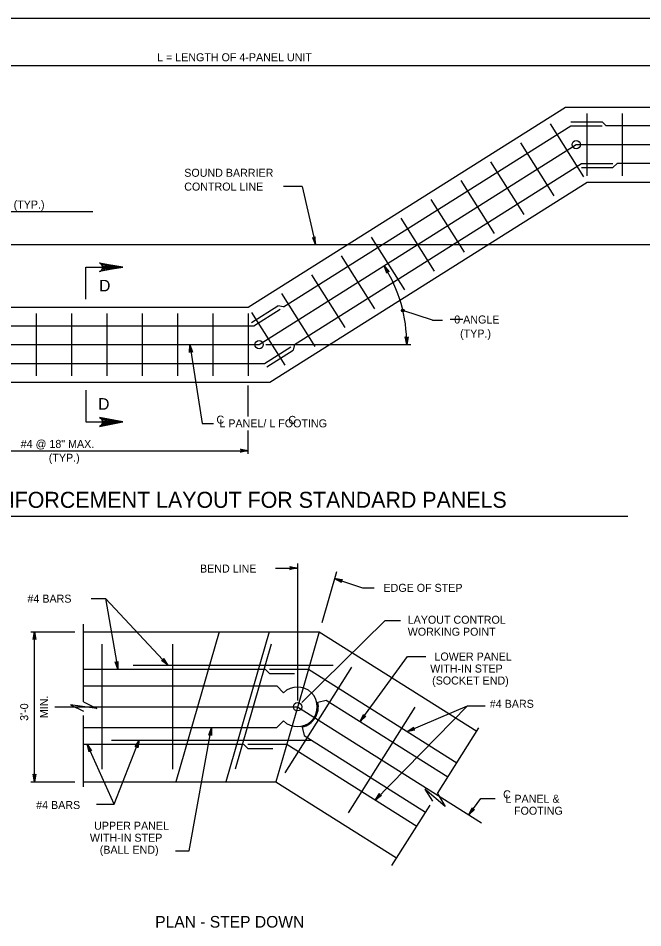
# Model space of a CAD drawing. Extents: x 3385 to 6532, y -616 to 1166.
# Drawn here: x 4903.8 to 5143.7, y -386.6 to -37.3 of the extents above; entities that cross this region are included whole.
import ezdxf

# ---------------------------------------------------------------- set-up
doc = ezdxf.new("R2010")
doc.units = 0
doc.layers.add('1', color=7, linetype='Continuous')
doc.layers.add('2', color=7, linetype='Continuous')

msp = doc.modelspace()

# ---------------------------------------------------------------- linework, layer by layer
at = {"layer": '1'}
for p, q in [((4730.55, -55.48), (5262.17, -55.48)), ((4992.2, -148.26), (5114.01, -71.46)), ((5114.01, -71.46), (5266.33, -71.46)), ((5122.33, -97.86), (5122.33, -73.86)), ((5135.9, -97.86), (5135.9, -73.86)), ((5005.79, -148.2), (5116.09, -78.66)), ((5121.05, -98.23), (5108.25, -77.93)), ((5116.09, -77.06), (5128.1, -77.06)), ((5116.09, -78.66), (5128.1, -78.66)), ((5129.7, -78.66), (5128.1, -77.06)), ((5264.25, -78.66), (5129.7, -78.66)), ((4996.36, -162.66), (5118.17, -85.86)), ((5096.75, -85.18), (5109.55, -105.48)), ((5118.17, -85.86), (5262.17, -85.86)), ((5118.17, -85.86), (5118.17, -85.86)), ((5009.95, -162.6), (5120.25, -93.06)), ((5085.28, -92.41), (5098.08, -112.71)), ((5120.25, -93.06), (5132.26, -93.06)), ((5133.86, -93.06), (5132.26, -94.66)), ((5260.09, -93.06), (5133.86, -93.06)), ((5120.25, -94.66), (5132.26, -94.66)), ((5000.52, -177.06), (5122.33, -100.26)), ((5073.8, -99.65), (5086.6, -119.95)), ((5122.33, -100.26), (5258.01, -100.26)), ((5012.92, -101.9), (5005.74, -101.9)), ((5012.92, -101.9), (5018.05, -124.26)), ((5062.33, -106.88), (5075.13, -127.18)), ((4847.16, -111.55), (4932.51, -111.55)), ((5050.85, -114.12), (5063.65, -134.42)), ((5039.38, -121.35), (5052.18, -141.65)), ((4707.43, -124.26), (5285.01, -124.26)), ((5027.9, -128.58), (5040.7, -148.89)), ((4929.77, -145.22), (4929.77, -132.95)), ((4929.77, -132.95), (4944.03, -132.95)), ((5016.43, -135.82), (5029.23, -156.12)), ((5004.95, -143.05), (5017.76, -163.36)), ((4856.52, -148.26), (4992.2, -148.26)), ((4993.43, -154.1), (5003.58, -147.7)), ((4994.28, -155.46), (5004.43, -149.06)), ((5005.79, -148.2), (5003.58, -147.7)), ((5063.01, -153.23), (5051.57, -149.56)), ((4910.78, -150.66), (4910.78, -174.66)), ((4924.34, -150.66), (4924.34, -174.66)), ((4937.91, -150.66), (4937.91, -174.66)), ((4951.47, -150.66), (4951.47, -174.66)), ((4965.04, -150.66), (4965.04, -174.66)), ((4978.6, -150.66), (4978.6, -174.66)), ((4992.2, -150.66), (4992.2, -174.66)), ((4993.48, -150.29), (5006.28, -170.59)), ((5063.01, -153.23), (5066.77, -153.23)), ((5074.59, -153.03), (5069.8, -153.03)), ((4868.04, -155.46), (4994.28, -155.46)), ((4852.36, -162.66), (4996.36, -162.66)), ((4969.74, -162.66), (4974.51, -193.01)), ((4996.36, -162.66), (4996.36, -162.66)), ((4998.44, -169.86), (5008.6, -163.46)), ((4998.89, -162.66), (5054.67, -162.66)), ((5009.95, -162.6), (5009.45, -164.81)), ((4999.3, -171.21), (5009.45, -164.81)), ((4863.88, -169.86), (4998.44, -169.86)), ((4848.2, -177.06), (5000.52, -177.06)), ((4929.77, -180.11), (4929.77, -192.37)), ((4992.2, -190.24), (4992.2, -178.37)), ((4929.77, -192.37), (4944.03, -192.37)), ((4974.51, -193.01), (4978.8, -193.01)), ((4992.2, -204.62), (4992.2, -195.66)), ((4856.52, -203.38), (4992.2, -203.38)), ((4839.99, -228.57), (5138.02, -228.57)), ((5011.12, -246.71), (5011.12, -299.34)), ((5002.71, -248.48), (5011.12, -248.48)), ((5026.09, -249.9), (5020.43, -269.5)), ((5025.35, -252.47), (5036.11, -256.06)), ((5036.11, -256.06), (5040.52, -256.06)), ((4931.83, -260.15), (4937.4, -260.15)), ((4937.4, -260.15), (4942.09, -287.34)), ((4937.4, -260.15), (4961.31, -285.74)), ((5044.63, -268.76), (5012.83, -300.06)), ((5050.61, -268.76), (5044.63, -268.76)), ((4928.9, -299.84), (4928.9, -270.06)), ((4908.72, -272.94), (4925.58, -272.94)), ((4910.11, -330.54), (4910.11, -272.94)), ((4928.9, -272.94), (5019.44, -272.94)), ((4981.04, -272.94), (4964.39, -330.54)), ((5000.24, -272.94), (4983.59, -330.54)), ((5019.44, -272.94), (5013.23, -294.44)), ((5019.44, -272.94), (5079.98, -311.11)), ((4936.08, -325.74), (4936.08, -277.74)), ((4963.22, -325.74), (4963.22, -277.74)), ((5000.99, -277.74), (4987.12, -325.74)), ((5035.15, -307.43), (5053.32, -282.46)), ((5053.32, -282.46), (5060.4, -282.46)), ((4947.98, -285.74), (5024.78, -285.74)), ((4928.9, -287.34), (4998.72, -287.34)), ((5000.32, -288.94), (4998.72, -287.34)), ((5000.32, -287.34), (5015.28, -287.34)), ((5000.32, -288.94), (5010.01, -288.94)), ((5006.33, -327.09), (5031.93, -286.49)), ((5015.28, -287.34), (5072.28, -323.28)), ((4928.9, -293.74), (5003.12, -293.74)), ((5003.12, -293.74), (5005.74, -296.37)), ((5013.23, -294.44), (5009.01, -309.04)), ((5018.92, -299.97), (5022.15, -299.24)), ((5022.16, -299.24), (5068.87, -328.69)), ((4917.93, -301.74), (5011.12, -301.74)), ((5011.12, -301.74), (5081.77, -346.29)), ((5011.12, -301.74), (5011.12, -301.74)), ((5030.69, -342.45), (5056.29, -301.85)), ((5040.88, -337.53), (5076.35, -301.38)), ((5053.22, -311.27), (5076.35, -301.38)), ((5076.35, -301.38), (5083.16, -301.38)), ((4928.9, -332.53), (4928.9, -305.09)), ((5003.12, -309.74), (5005.74, -307.12)), ((4928.9, -309.74), (5003.12, -309.74)), ((4969.53, -357.04), (4978.08, -309.74)), ((5009.01, -309.04), (5002.79, -330.54)), ((5012.88, -309.54), (5013.62, -312.78)), ((5064.85, -335.04), (5080.77, -309.87)), ((5013.62, -312.78), (5060.31, -342.22)), ((4928.9, -316.14), (4990.4, -316.14)), ((4940.7, -339.18), (4930.31, -316.14)), ((4939.66, -314.54), (5016.46, -314.54)), ((4940.7, -339.18), (4950.33, -314.54)), ((4992, -317.74), (4990.4, -316.14)), ((4992, -316.14), (5006.96, -316.14)), ((4992, -317.74), (5001.69, -317.74)), ((5006.96, -316.14), (5056.89, -347.62)), ((4908.72, -330.54), (4925.58, -330.54)), ((4928.9, -330.54), (5002.79, -330.54)), ((5002.79, -330.54), (5049.19, -359.79)), ((5076.89, -343.21), (5081.48, -336.89)), ((5081.48, -336.89), (5087.06, -336.89)), ((4933.89, -339.18), (4940.7, -339.18)), ((5047.37, -362.66), (5062.04, -339.48)), ((4964.28, -357.04), (4969.53, -357.04))]:
    msp.add_line(p, q, dxfattribs=at)
for points in [[(5018.05, -124.26), (5017.93, -121.23), (5017.82, -121.49), (5017.66, -121.65), (5017.47, -121.72), (5017.27, -121.74), (5017.04, -121.66), (5016.84, -121.48), (5018.05, -124.26), (5017.04, -121.66), (5017.27, -121.74), (5018.05, -124.26), (5017.47, -121.72), (5017.66, -121.65), (5018.05, -124.26), (5017.82, -121.49)], [(4944.03, -132.95), (4935.09, -134.63), (4935.43, -134.39), (4935.78, -134.15), (4935.95, -133.85), (4936.13, -133.55), (4936.18, -133.25), (4936.23, -132.95), (4936.18, -132.65), (4936.13, -132.35), (4935.95, -132.05), (4935.78, -131.75), (4935.43, -131.51), (4935.09, -131.27), (4944.03, -132.95), (4935.43, -131.51), (4935.78, -131.75), (4944.03, -132.95), (4935.95, -132.05), (4936.13, -132.35), (4944.03, -132.95), (4936.18, -132.65), (4936.23, -132.95), (4944.03, -132.95), (4936.18, -133.25), (4936.13, -133.55), (4944.03, -132.95), (4935.95, -133.85), (4935.78, -134.15), (4944.03, -132.95), (4935.43, -134.39)], [(5044.36, -132.4), (5046.36, -134.68), (5046.1, -134.56), (5045.87, -134.56), (5045.68, -134.63), (5045.53, -134.77), (5045.42, -134.97), (5045.4, -135.25), (5044.36, -132.4), (5045.42, -134.97), (5045.53, -134.77), (5044.36, -132.4), (5045.68, -134.63), (5045.87, -134.56), (5044.36, -132.4), (5046.1, -134.56)], [(5053.1, -162.66), (5052.52, -159.68), (5052.68, -159.91), (5052.88, -160.03), (5053.08, -160.06), (5053.28, -160.02), (5053.48, -159.9), (5053.64, -159.67), (5053.1, -162.66), (5053.48, -159.9), (5053.28, -160.02), (5053.1, -162.66), (5053.08, -160.06), (5052.88, -160.03), (5053.1, -162.66), (5052.68, -159.91)], [(4969.74, -162.66), (4970.76, -165.52), (4970.56, -165.32), (4970.35, -165.23), (4970.14, -165.23), (4969.95, -165.29), (4969.77, -165.44), (4969.65, -165.69), (4969.74, -162.66), (4969.77, -165.44), (4969.95, -165.29), (4969.74, -162.66), (4970.14, -165.23), (4970.35, -165.23), (4969.74, -162.66), (4970.56, -165.32)], [(4944.03, -192.37), (4935.09, -190.69), (4935.43, -190.93), (4935.78, -191.17), (4935.95, -191.47), (4936.13, -191.77), (4936.18, -192.07), (4936.23, -192.37), (4936.18, -192.67), (4936.13, -192.97), (4935.95, -193.27), (4935.78, -193.57), (4935.43, -193.81), (4935.09, -194.05), (4944.03, -192.37), (4935.43, -193.81), (4935.78, -193.57), (4944.03, -192.37), (4935.95, -193.27), (4936.13, -192.97), (4944.03, -192.37), (4936.18, -192.67), (4936.23, -192.37), (4944.03, -192.37), (4936.18, -192.07), (4936.13, -191.77), (4944.03, -192.37), (4935.95, -191.47), (4935.78, -191.17), (4944.03, -192.37), (4935.43, -190.93)], [(4992.2, -203.38), (4989.22, -203.93), (4989.45, -203.78), (4989.57, -203.58), (4989.6, -203.38), (4989.57, -203.18), (4989.45, -202.98), (4989.22, -202.82), (4992.2, -203.38), (4989.45, -202.98), (4989.57, -203.18), (4992.2, -203.38), (4989.6, -203.38), (4989.57, -203.58), (4992.2, -203.38), (4989.45, -203.78)], [(5011.12, -248.48), (5008.13, -249.04), (5008.36, -248.88), (5008.48, -248.68), (5008.52, -248.48), (5008.48, -248.28), (5008.36, -248.08), (5008.13, -247.92), (5011.12, -248.48), (5008.36, -248.08), (5008.48, -248.28), (5011.12, -248.48), (5008.52, -248.48), (5008.48, -248.68), (5011.12, -248.48), (5008.36, -248.88)], [(5025.35, -252.47), (5028.36, -252.89), (5028.22, -252.92), (5028.09, -252.96), (5028, -253.04), (5027.91, -253.12), (5027.87, -253.21), (5027.82, -253.29), (5027.8, -253.4), (5027.79, -253.5), (5027.81, -253.61), (5027.84, -253.72), (5027.92, -253.83), (5028, -253.95), (5025.35, -252.47), (5027.92, -253.83), (5027.84, -253.72), (5025.35, -252.47), (5027.81, -253.61), (5027.79, -253.5), (5025.35, -252.47), (5027.8, -253.4), (5027.82, -253.29), (5025.35, -252.47), (5027.87, -253.21), (5027.91, -253.12), (5025.35, -252.47), (5028, -253.04), (5028.09, -252.96), (5025.35, -252.47), (5028.22, -252.92)], [(4910.11, -272.94), (4910.67, -275.92), (4910.51, -275.69), (4910.31, -275.57), (4910.11, -275.54), (4909.91, -275.57), (4909.71, -275.69), (4909.55, -275.92), (4910.11, -272.94), (4909.71, -275.69), (4909.91, -275.57), (4910.11, -272.94), (4910.11, -275.54), (4910.31, -275.57), (4910.11, -272.94), (4910.51, -275.69)], [(4942.09, -287.34), (4941.03, -284.5), (4941.23, -284.7), (4941.45, -284.78), (4941.65, -284.78), (4941.84, -284.71), (4942.02, -284.56), (4942.14, -284.31), (4942.09, -287.34), (4942.02, -284.56), (4941.84, -284.71), (4942.09, -287.34), (4941.65, -284.78), (4941.45, -284.78), (4942.09, -287.34), (4941.23, -284.7)], [(4961.31, -285.74), (4958.87, -283.94), (4959.14, -284), (4959.37, -283.95), (4959.54, -283.84), (4959.66, -283.68), (4959.72, -283.46), (4959.68, -283.18), (4961.31, -285.74), (4959.72, -283.46), (4959.66, -283.68), (4961.31, -285.74), (4959.54, -283.84), (4959.37, -283.95), (4961.31, -285.74), (4959.14, -284)], [(4928.9, -299.84), (4934.09, -302.38), (4923.94, -301), (4928.9, -303.36)], [(5035.15, -307.43), (5036.45, -304.69), (5036.44, -304.97), (5036.53, -305.18), (5036.68, -305.32), (5036.86, -305.41), (5037.09, -305.44), (5037.35, -305.34), (5035.15, -307.43), (5037.09, -305.44), (5036.86, -305.41), (5035.15, -307.43), (5036.68, -305.32), (5036.53, -305.18), (5035.15, -307.43), (5036.44, -304.97)], [(4978.08, -309.74), (4978.1, -312.78), (4977.98, -312.52), (4977.8, -312.37), (4977.61, -312.3), (4977.41, -312.3), (4977.19, -312.38), (4977, -312.58), (4978.08, -309.74), (4977.19, -312.38), (4977.41, -312.3), (4978.08, -309.74), (4977.61, -312.3), (4977.8, -312.37), (4978.08, -309.74), (4977.98, -312.52)], [(5053.22, -311.27), (5055.75, -309.58), (5055.6, -309.82), (5055.57, -310.05), (5055.62, -310.24), (5055.73, -310.41), (5055.91, -310.55), (5056.19, -310.61), (5053.22, -311.27), (5055.91, -310.55), (5055.73, -310.41), (5053.22, -311.27), (5055.62, -310.24), (5055.57, -310.05), (5053.22, -311.27), (5055.6, -309.82)], [(4930.31, -316.14), (4932.05, -318.63), (4931.81, -318.49), (4931.58, -318.46), (4931.38, -318.51), (4931.21, -318.62), (4931.08, -318.81), (4931.03, -319.09), (4930.31, -316.14), (4931.08, -318.81), (4931.21, -318.62), (4930.31, -316.14), (4931.38, -318.51), (4931.58, -318.46), (4930.31, -316.14), (4931.81, -318.49)], [(4950.33, -314.54), (4949.76, -317.52), (4949.7, -317.25), (4949.56, -317.07), (4949.38, -316.96), (4949.18, -316.92), (4948.95, -316.96), (4948.72, -317.12), (4950.33, -314.54), (4948.95, -316.96), (4949.18, -316.92), (4950.33, -314.54), (4949.38, -316.96), (4949.56, -317.07), (4950.33, -314.54), (4949.7, -317.25)], [(4910.11, -330.54), (4909.55, -327.56), (4909.71, -327.79), (4909.91, -327.91), (4910.11, -327.94), (4910.31, -327.91), (4910.51, -327.79), (4910.67, -327.56), (4910.11, -330.54), (4910.51, -327.79), (4910.31, -327.91), (4910.11, -330.54), (4910.11, -327.94), (4909.91, -327.91), (4910.11, -330.54), (4909.71, -327.79)], [(5040.88, -337.53), (5042.57, -335.01), (5042.52, -335.29), (5042.58, -335.51), (5042.7, -335.68), (5042.87, -335.79), (5043.1, -335.85), (5043.37, -335.79), (5040.88, -337.53), (5043.1, -335.85), (5042.87, -335.79), (5040.88, -337.53), (5042.7, -335.68), (5042.58, -335.51), (5040.88, -337.53), (5042.52, -335.29)], [(5064.85, -335.04), (5067.87, -339.96), (5060.03, -333.37), (5062.96, -338.02)], [(5076.89, -343.21), (5078.19, -340.47), (5078.19, -340.75), (5078.28, -340.96), (5078.42, -341.11), (5078.6, -341.2), (5078.83, -341.22), (5079.1, -341.13), (5076.89, -343.21), (5078.83, -341.22), (5078.6, -341.2), (5076.89, -343.21), (5078.42, -341.11), (5078.28, -340.96), (5076.89, -343.21), (5078.19, -340.75)]]:
    msp.add_lwpolyline(points, dxfattribs=at)
for centre, radius in [((5118.17, -85.86), 1.6), ((5051.57, -149.56), 0.533), ((5051.57, -149.56), 0.267), ((4996.36, -162.66), 1.6), ((5011.12, -301.74), 1.6)]:
    msp.add_circle(centre, radius, dxfattribs=at)
for centre, radius, start, end in [((4996.36, -162.66), 56.74, 0, 32.2309), ((5011.12, -301.74), 7.6, 225, 135), ((5011.12, -301.74), 8, 282.7683, 12.7708)]:
    msp.add_arc(centre, radius, start, end, dxfattribs=at)
at = {"layer": '2'}
msp.add_line((4642.34, -37.31), (5428.34, -37.31), dxfattribs=at)

# ---------------------------------------------------------------- texts
at = {"layer": '1'}
for s, height, p in [('L = LENGTH OF 4-PANEL UNIT', 3.0721, (4957.18, -53.85)), ('SOUND BARRIER', 3.0721, (4967.61, -98.2)), ('CONTROL LINE', 3.0721, (4967.61, -103.51)), ('SPLICE #4 BAR (TYP.)', 3.0721, (4871.04, -110.4)), ('D', 4.45, (4934.94, -142.23)), ('0 ANGLE', 3.072, (5071.32, -154.55)), ('(TYP.)', 3.072, (5073.56, -159.93)), ('D', 4.45, (4934.57, -187.66)), ('C', 3.07, (4979.98, -192.99)), ('L PANEL/ L FOOTING', 3.0721, (4981.12, -194.43)), ('C', 3.07, (5007.61, -193.1)), ('#4 @ 18" MAX.', 3.0721, (4904.8, -202.32)), ('(TYP.)', 3.072, (4915.58, -207.63)), ('FOOTING REINFORCEMENT LAYOUT FOR STANDARD PANELS', 6.144, (4843.14, -225.33)), ('BEND LINE', 3.072, (4973.67, -250.2)), ('EDGE OF STEP', 3.0721, (5044.13, -257.59)), ('#4 BARS', 3.072, (4907.4, -261.74)), ('LAYOUT CONTROL', 3.0721, (5053.44, -269.84)), ('WORKING POINT', 3.0721, (5053.44, -274.44)), ('LOWER PANEL', 3.0721, (5063.71, -283.97)), ('WITH-IN STEP', 3.0721, (5062.09, -288.58)), ('(SOCKET END)', 3.0721, (5062.81, -293.18)), ('#4 BARS', 3.072, (5084.98, -302.12)), ('C', 3.07, (5090.09, -336.88)), ('#4 BARS', 3.072, (4910.74, -340.98)), ('L PANEL &', 3.072, (5091, -338.57)), ('FOOTING', 3.072, (5094.28, -343.18)), ('UPPER PANEL', 3.0721, (4932.99, -348.94)), ('WITH-IN STEP', 3.0721, (4931.37, -353.55)), ('(BALL END)', 3.072, (4935.16, -358.16)), ('PLAN - STEP DOWN', 4.4801, (4956.45, -386.54))]:
    msp.add_text(s, height=height, dxfattribs=at).set_placement(p)
for s, p in [('MIN.', (4915.22, -306.09)), ("3'-0", (4907.67, -307.14))]:
    msp.add_text(s, height=3.072, rotation=90, dxfattribs=at).set_placement(p)

doc.saveas('drawing.dxf')
